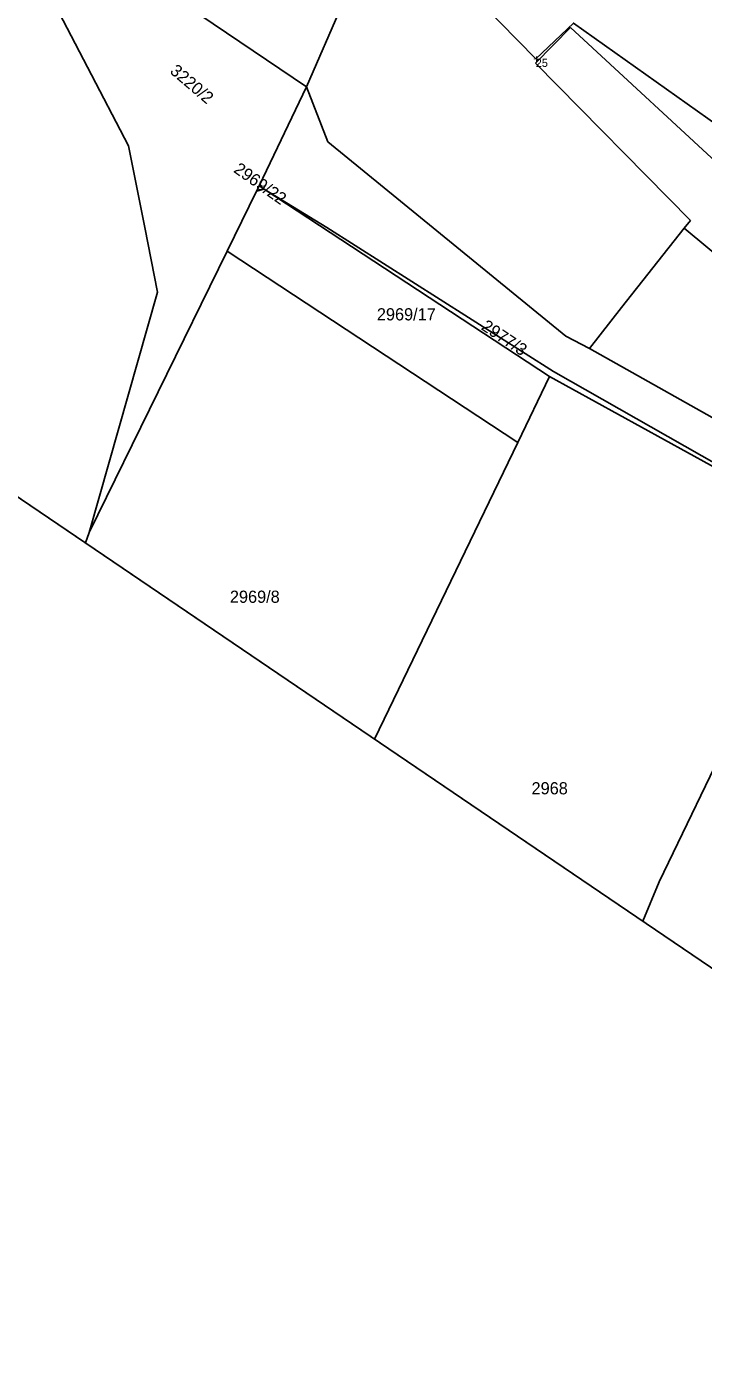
# Model space of a CAD drawing. Extents: x -621058 to -620023, y -1122866 to -1122030.
# Drawn here: x -620345 to -620261.7, y -1122865.7 to -1122701.3 of the extents above; entities that cross this region are included whole.
import ezdxf

# ---------------------------------------------------------------- set-up
doc = ezdxf.new("R2010")
doc.units = 0
for name, color, linetype in [('060604_ROZVODY_SEE', 7, 'Continuous'), ('BODY', 7, 'Continuous'), ('BODY POPIS', 7, 'Continuous'), ('RÁMY', 7, 'Continuous'), ('Vrstva 53', 7, 'Continuous'), ('Vrstva 55', 7, 'Continuous'), ('Vrstva 57', 7, 'Continuous')]:
    doc.layers.add(name, color=color, linetype=linetype)

msp = doc.modelspace()

# ---------------------------------------------------------------- linework, layer by layer
at = {"layer": '060604_ROZVODY_SEE'}
msp.add_lwpolyline([(-620243.03, -1122716), (-620248.32, -1122722.77), (-620259.89, -1122713.57), (-620277.71, -1122700.9), (-620282.35, -1122705.3), (-620297.82, -1122689.49), (-620304.22, -1122684.86), (-620310.82, -1122680.06), (-620316.82, -1122675.99), (-620322.23, -1122672.32), (-620326.63, -1122669.41), (-620343.18, -1122658.46), (-620368.5, -1122642.9), (-620411.56, -1122614.92), (-620424.16, -1122607.09), (-620443.53, -1122595), (-620444.24, -1122596.15)], dxfattribs=at)
at = {"layer": 'RÁMY'}
for points in [[(-620974.7, -1122152.91), (-620106.07, -1122742.82), (-620189.51, -1122865.67), (-621058.13, -1122275.76)], [(-620887.83, -1122211.9), (-620106.07, -1122742.82), (-620189.51, -1122865.67), (-620971.26, -1122334.75)]]:
    msp.add_lwpolyline(points, close=True, dxfattribs=at)
at = {"layer": 'Vrstva 53'}
for p, q in [((-620310.57, -1122708.76), (-620306.2, -1122698.65)), ((-620278.07, -1122701.42), (-620282.38, -1122705.84)), ((-620278.07, -1122701.42), (-620246.12, -1122731.05)), ((-620263.28, -1122725.23), (-620282.38, -1122705.84)), ((-620307.94, -1122715.53), (-620310.57, -1122708.76)), ((-620278.65, -1122739.48), (-620307.94, -1122715.53)), ((-620271.78, -1122735.94), (-620264.06, -1122726.18)), ((-620263.28, -1122725.23), (-620264.06, -1122726.18)), ((-620251.62, -1122736.54), (-620264.06, -1122726.18)), ((-620275.74, -1122741.01), (-620271.78, -1122735.94)), ((-620278.65, -1122739.48), (-620275.74, -1122741.01)), ((-620251.9, -1122754.44), (-620275.74, -1122741.01))]:
    msp.add_line(p, q, dxfattribs=at)
at = {"layer": 'Vrstva 55'}
for p, q in [((-620368.46, -1122669.58), (-620310.57, -1122708.76)), ((-620342.37, -1122697.07), (-620337.56, -1122706.31)), ((-620310.57, -1122708.76), (-620306.2, -1122698.65)), ((-620278.07, -1122701.42), (-620282.38, -1122705.84)), ((-620246.12, -1122731.05), (-620278.07, -1122701.42)), ((-620337.56, -1122706.31), (-620332.51, -1122716.01)), ((-620282.38, -1122705.84), (-620263.28, -1122725.23)), ((-620310.57, -1122708.76), (-620316.42, -1122720.94)), ((-620310.57, -1122708.76), (-620307.94, -1122715.53)), ((-620332.51, -1122716.01), (-620330.51, -1122726.08)), ((-620307.94, -1122715.53), (-620278.65, -1122739.48)), ((-620320.37, -1122729), (-620316.74, -1122721.6)), ((-620316.74, -1122721.6), (-620316.42, -1122720.94)), ((-620316.74, -1122721.6), (-620315.79, -1122721.36)), ((-620316.42, -1122720.94), (-620315.79, -1122721.36)), ((-620308.1, -1122726.09), (-620315.79, -1122721.36)), ((-620315.79, -1122721.36), (-620280.66, -1122744.45)), ((-620330.51, -1122726.08), (-620328.93, -1122734.05)), ((-620280.18, -1122743.84), (-620308.1, -1122726.09)), ((-620271.78, -1122735.94), (-620264.06, -1122726.18)), ((-620263.28, -1122725.23), (-620264.06, -1122726.18)), ((-620251.62, -1122736.54), (-620264.06, -1122726.18)), ((-620337.36, -1122763.66), (-620320.37, -1122729)), ((-620320.37, -1122729), (-620284.57, -1122752.56)), ((-620328.93, -1122734.05), (-620337.36, -1122763.66)), ((-620275.74, -1122741.01), (-620271.78, -1122735.94)), ((-620278.65, -1122739.48), (-620275.74, -1122741.01)), ((-620275.74, -1122741.01), (-620251.9, -1122754.44)), ((-620280.66, -1122744.45), (-620284.57, -1122752.56)), ((-620280.66, -1122744.45), (-620246.32, -1122763.41)), ((-620280.18, -1122743.84), (-620246.23, -1122763.17)), ((-620284.57, -1122752.56), (-620302.21, -1122789.13)), ((-620337.36, -1122763.66), (-620337.81, -1122764.95)), ((-620246.32, -1122763.41), (-620267.15, -1122806.71)), ((-620267.15, -1122806.71), (-620269.18, -1122811.56))]:
    msp.add_line(p, q, dxfattribs=at)

# ---------------------------------------------------------------- texts
at = {"layer": 'BODY'}
msp.add_text('+', height=1, dxfattribs=at).set_placement((-620282.68, -1122705.8))
at = {"layer": 'BODY POPIS'}
msp.add_text('25', height=1, dxfattribs=at).set_placement((-620282.35, -1122706.3))
at = {"layer": 'Vrstva 57'}
for s, rotation, p in [('3220/2', 319.5, (-620327.51, -1122706.97)), ('2969/22', 324.8459, (-620319.67, -1122719.19)), ('2977/3', 326.397, (-620289.18, -1122738.58))]:
    msp.add_text(s, height=1.5, rotation=rotation, dxfattribs=at).set_placement(p)
for s, p in [('2969/17', (-620301.92, -1122737.53)), ('2969/8', (-620320.02, -1122772.33)), ('2968', (-620282.87, -1122795.93))]:
    msp.add_text(s, height=1.5, dxfattribs=at).set_placement(p)

doc.saveas('drawing.dxf')
